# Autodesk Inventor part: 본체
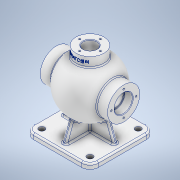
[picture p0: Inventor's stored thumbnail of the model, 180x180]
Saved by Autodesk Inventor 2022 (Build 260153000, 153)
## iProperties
Created: 2024-04
Part Number: 본체
Material: 알루미늄 6061
Document SubType Name: Modeling
Designer: Admin
Mass: 1526.53 g
Surface Area: 1174.37 cm^2
Volume: 565.38 cm^3
Density: 2.7 g/cm^3
Appearance: 알루미늄 - 평지
Author: Admin
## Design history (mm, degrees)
sketch "스케치1"
  geometry: L1 (-75.6, 0)-(75.6, 0) reference; L2 (0, -10.8)-(0, 64.8) reference; L3 (-54, 0)-(54, 0); A1 r 54 centre (0, 0) between (54, 0) and (-54, 0); 1 further point
  constraints: 2 end point, 2 point on circle, 1 centre point, 1 coincident, 1 horizontal, 1 symmetric about line
  dimensions: "d7" = 54 radius of A1; "d11" = 108 distance of L3.start L3.end
revolve "회전1" sketch "스케치1" stored, may be unused: angle "d9" = 90 deg
node "작업 평면2"
sketch "스케치2"
  geometry: C1 r 31 at (0, 0); 1 further point
  constraints: 1 centre point, 1 coincident
  dimensions: "d13" = 62 diameter of C1
extrude "돌출1" join sketch "스케치2" stored distance "d14" = 10; taper "d15" = 0 deg
node "작업 평면3"
sketch "스케치3"
  geometry: L1 (62.5, -62.5)-(-62.5, -62.5); L2 (-62.5, -62.5)-(-62.5, 62.5); L3 (-62.5, 62.5)-(62.5, 62.5); L4 (62.5, 62.5)-(62.5, -62.5); L5 (62.5, -62.5)-(-62.5, 62.5); L6 (-62.5, -62.5)-(62.5, 62.5); 1 further point
  constraints: 12 end point, 2 midpoint, 2 parallel, 1 horizontal, 1 perpendicular
  dimensions: "d17" = 125 distance of L2.end L3.end; "d18" = 125 distance of L1.end L2.end
extrude "돌출2" join sketch "스케치3" distance "d19" = 10; taper "d20" = 0 deg
sketch "스케치4"
  geometry: L1 (-112.8, 0)-(81.8, 0) reference; L2 (0, -87.5)-(0, 87.5) reference; L3 (-75, -50.5)-(0, -23.202); L4 (0, -23.202)-(0, 23.202); L5 (0, 23.202)-(-75, 50.5); L6 (-75, 62.5)-(-75, -62.5) reference; L7 (-85, -62.5)-(-75, -62.5) reference; L8 (-75, -50.5)-(-75, 50.5); 1 further point
  constraints: 8 end point, 2 point on line, 1 collinear, 1 midpoint, 1 vertical, 1 other
  dimensions: "d21" = 12 distance of L3.start L6.end; "d23" = 20 deg angle of L7 L3
extrude "돌출3" join sketch "스케치4" stored distance "d24" = 8; taper "d25" = 0 deg
sketch "스케치5"
  geometry: L1 (-91, 0)-(91, 0) reference; L2 (0, -112.8)-(0, 81.8) reference; L3 (50.5, -75)-(23.202, 0); L4 (23.202, 0)-(-23.202, 0); L5 (-23.202, 0)-(-50.5, -75); L6 (-62.5, -75)-(62.5, -75) reference; L7 (62.5, -85)-(62.5, -75) reference; L8 (50.5, -75)-(-50.5, -75); 1 further point
  constraints: 8 end point, 2 point on line, 1 collinear, 1 horizontal, 1 midpoint, 1 other
  dimensions: "d26" = 20 deg angle of L7 L3; "d27" = 12 distance of L6.end L3.start
extrude "돌출4" join sketch "스케치5" stored distance "d28" = 8; taper "d29" = 0 deg
sketch "스케치6"
  geometry: L1 (-91, 0)-(91, 0) reference; L2 (0, -112.8)-(0, 81.8) reference; L3 (44, 0)-(-44, 0); L4 (-44.215, -31)-(-44.215, 31) reference; A1 r 44 centre (0, 0) between (44, 0) and (-44, 0); 1 further point
  constraints: 2 end point, 2 point on circle, 2 point on line, 1 centre point, 1 coincident, 1 perpendicular, 1 symmetric about line
  dimensions: "d30" = 44 radius of A1
revolve "회전2" sketch "스케치6" stored, may be unused: angle "d31" = 90 deg
sketch "스케치7"
  geometry: C1 r 17.5 at (0, 0); 1 further point
  constraints: 1 centre point, 1 coincident
  dimensions: "d32" = 35 diameter of C1
extrude "돌출5" cut sketch "스케치7" distance "d33" = 16; taper "d34" = 0 deg
sketch "스케치8"
  geometry: C1 r 15 at (0, 0); 1 further point
  constraints: 1 centre point, 1 coincident
  dimensions: "d35" = 30 diameter of C1
extrude "돌출6" cut sketch "스케치8" stored distance "d36" = 16; taper "d37" = 0 deg
node "작업 평면7"
sketch "스케치9"
  geometry: C1 r 27 at (0, 0); 1 further point
  constraints: 1 centre point, 1 coincident
  dimensions: "d41" = 54 diameter of C1
extrude "돌출7" join sketch "스케치9" stored distance "d42" = 10; taper "d43" = 0 deg
sketch "스케치10"
  geometry: C1 r 13 at (0, 0); 1 further point
  constraints: 1 centre point, 1 coincident
  dimensions: "d44" = 26 diameter of C1
extrude "돌출8" cut sketch "스케치10" stored distance "d45" = 10; taper "d46" = 0 deg
sketch "스케치11"
  geometry: L1 (-91, 0)-(91, 0) reference; L2 (0, 87.5)-(0, -87.5) reference; 5 further points
  constraints: 4 point on line, 2 symmetric about line
  dimensions: "d48" = 40 distance of point (20, 0) point (-20, 0); "d91" = 40 distance of point (0, -20) point (0, 20)
hole "구멍1" sketch "스케치11" at (20, 0), (-20, 0), (0, 20), (0, -20) diameter "d49" = 3.242; stored, may be unused: countersink angle "d53" = 90 deg, drill point angle "d55" = 118 deg; dims "d50" = 9, "d51" = 4, "d52" = 2, "d54" = 11
sketch "스케치12"
  geometry: L1 (0, -115)-(0, 95) reference; L2 (87.5, 0)-(-87.5, 0) reference; 5 further points
  constraints: 4 point on line, 2 symmetric about line
  dimensions: "d56" = 48 distance of point (24, 0) point (-24, 0); "d57" = 48 distance of point (0, 24) point (0, -24)
hole "구멍2" sketch "스케치12" at (-24, 0), (0, -24), (24, 0), (0, 24) diameter "d58" = 3.242; stored, may be unused: countersink angle "d62" = 90 deg, drill point angle "d64" = 118 deg; dims "d59" = 12, "d60" = 4, "d61" = 2, "d63" = 15
fillet "모깎기1" dims "d65" = 16
fillet "모깎기2" dims "d66" = 3
sketch "스케치13"
  geometry: L1 (-91, 0)-(91, 0) reference; L2 (46.5, 62.5)-(-46.5, 62.5) reference; L3 (62.5, -46.5)-(62.5, 46.5) reference; L4 (-46.5, -62.5)-(46.5, -62.5) reference; L5 (-62.5, 46.5)-(-62.5, -46.5) reference; L6 (0, 62.5)-(0, -62.5); A1 r 16 centre (-46.5, 46.5) between (-46.5, 62.5) and (-62.5, 46.5) reference; A2 r 16 centre (46.5, 46.5) between (62.5, 46.5) and (46.5, 62.5) reference; A3 r 16 centre (46.5, -46.5) between (46.5, -62.5) and (62.5, -46.5) reference; A4 r 16 centre (-46.5, -46.5) between (-62.5, -46.5) and (-46.5, -62.5) reference; 5 further points
  constraints: 4 coincident, 2 end point, 2 midpoint
hole "구멍3" sketch "스케치13" at (-46.5, 46.5), (46.5, 46.5), (46.5, -46.5), (-46.5, -46.5) diameter "d71" = 11; stored, may be unused: countersink angle "d75" = 90 deg, drill point angle "d77" = 118 deg; dims "d72" = 12, "d73" = 4, "d74" = 2, "d76" = 15
fillet "모깎기3" dims "d78" = 3
fillet "모깎기4" dims "d79" = 3
chamfer "모따기1" distance "d80" = 1; stored, may be unused: second distance "d81" = 2, angle "d82" = 45 deg
fillet "모깎기5" dims "d83" = 3
fillet "모깎기6" dims "d84" = 3
fillet "모깎기7" dims "d85" = 3
fillet "모깎기8" dims "d86" = 0.6
node "작업 평면8"
sketch "스케치14"
  geometry: L1 (-27, 65)-(27, 65) reference; L2 (0, -115)-(0, 95) reference; 2 further points
  constraints: 1 point on line, 1 other
  dimensions: "d88" = 9 distance from line of L1 point (0, 56)
feature "엠보싱1" sketch "스케치14" dims "d89" = 0.5, "d90" = 0
node "솔리드1"
mirror "미러1"
mirror "미러2"
mirror "미러3"
mirror "미러4"
node "투영된 루프1"
feature "A9D066F2-1C7D-4E18-AEED-F7BC21143FA4" dims "d49" = 3.242, "d50" = 9, "d51" = 4, "d52" = 2, "d53" = 90 deg, "d54" = 11, "d55" = 118 deg
other parameters: "d12" = 65, "d16" = -85, "d87" = 108.75
